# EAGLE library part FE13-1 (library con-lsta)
FEMALE HEADER
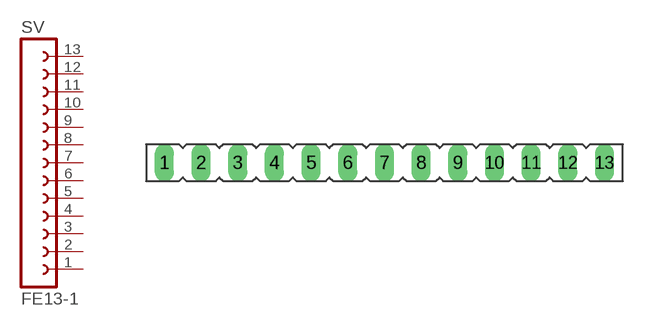
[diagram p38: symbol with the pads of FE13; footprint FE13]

Designator prefix SV

## FE13-1 (OC_FARNELL: unknown; OC_NEWARK: unknown)  [FE13]
1  1  pas
2  2  pas
3  3  pas
4  4  pas
5  5  pas
6  6  pas
7  7  pas
8  8  pas
9  9  pas
10  10  pas
11  11  pas
12  12  pas
13  13  pas

## Footprint FE13 (pad centres in mm)
FEMALE HEADER
drill 0.813 long: 1 -15.24,0; 2 -12.7,0; 3 -10.16,0; 4 -7.62,0; 5 -5.08,0; 6 -2.54,0; 7 0,0; 8 2.54,0; 9 5.08,0; 10 7.62,0; 11 10.16,0; 12 12.7,0; 13 15.24,0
